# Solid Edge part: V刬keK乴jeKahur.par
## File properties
Author: Egon 815
Template: Normal.par
Last saved by: Egon 815
Revision: 4
Application: Solid Edge
Accuracy: 0,990
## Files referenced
..\Laev.asm
.C:\Kool\3D Modelleerimine\LaevaJoonis\Laev.asm
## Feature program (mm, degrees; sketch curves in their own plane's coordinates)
sketch for "unnamed Protrusion 1" plane through (0, 0, 7184.8312) normal (0, 0, 1) x-axis (1, 0, 0)
  circle centre (11893.7444, -24290.4261) radius 1091.1039
extrude "unnamed Protrusion 1" add to key point along -normal
sketch for "unnamed Cutout 1" plane through (0, -24290.4261, 0) normal (0, -1, 0) x-axis (1, 0, 0)
  line (12191.9132, 6960.694) -> (12191.912, 5564.3945)
  line (12191.912, 5564.3945) -> (11595.5763, 5564.3945)
  line (11595.5763, 5564.3945) -> (11595.5763, 6960.694)
  line (11595.5763, 6960.694) -> (12191.9132, 6960.694)
extrude "unnamed Cutout 1" cut through along +normal
lofted protrusion "unnamed LoftedProtrusion 1"
chamfer "Chamfer_4" setback 150
chamfer "Chamfer_5" setback 50
sketch for "unnamed Cutout 2" plane through (0, -28685.0118, 0) normal (0, -1, 0) x-axis (1, 0, 0)
  circle centre (11893.7444, 6258.1105) radius 125
extrude "unnamed Cutout 2" cut to key point along -normal
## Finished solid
Body 1: solid body, 18 faces, 34 edges, 18 vertices.
  Faces by surface: plane 11, cone 3, cylinder 2, spline 2
  Edges by curve: line 14, circle 11, curve on surface 7, intersection 2
Bounding box of the edges (mm; curved faces can reach further): 2182.208 x 5485.690 x 2152.254, from (10802.6405, -28685.0118, 5032.5774) to (12984.8483, -23199.3222, 7184.8312).
Cylindrical faces by radius (mm): R125 x1, R1091.1039 x1
Conical faces (half-angle, radius in mm at the cone's reference point): 45 deg R1091.1039 x3
Planar faces by outward normal: +x 1, +z 2, -x 1, -y 4, -z 2, oblique 1
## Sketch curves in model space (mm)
line (12191.912, -24290.4261, 5564.3945) -> (11595.5763, -24290.4261, 5564.3945)
line (11595.5763, -24290.4261, 5564.3945) -> (11595.5763, -24290.4261, 6960.694)
line (11595.5763, -24290.4261, 6960.694) -> (12191.9132, -24290.4261, 6960.694)
line (12191.9132, -24290.4261, 6960.694) -> (12191.912, -24290.4261, 5564.3945)
circle centre (11893.7444, -28685.0118, 6258.1105) radius 125
circle centre (11893.7444, -28685.0118, 6258.1105) radius 195.8119
line (11893.7444, -28685.0118, 6062.2986) -> (11893.7444, -28685.0118, 6453.9224)
circle centre (11893.7444, -24290.4261, 6262.5608) radius 298.1681
line (11893.7444, -24290.4261, 6560.7289) -> (11893.7444, -24290.4261, 5964.3926)
line (11893.7444, -28685.0118, 6062.2986) -> (11893.7444, -25409.6126, 5964.3926)
line (11893.7444, -28685.0118, 6062.2986) -> (11893.7444, -28685.0118, 6453.9224)
line (11893.7444, -28685.0118, 6453.9224) -> (11893.7444, -25409.6126, 6560.7289)
line (11893.7444, -25409.6126, 6560.7289) -> (11893.7444, -25409.6126, 5964.3926)
line (11893.7444, -25641.0267, 7085.8609) -> (11893.7444, -23567.2005, 7085.8609)
line (11893.7444, -23567.2005, 7085.8609) -> (11893.7444, -23567.2005, 5032.5774)
line (11893.7444, -23567.2005, 5032.5774) -> (11893.7444, -25641.0267, 5032.5774)
line (11893.7444, -25641.0267, 5032.5774) -> (11893.7444, -25641.0267, 7085.8609)
circle centre (11893.7444, -24290.4261, 7184.8312) radius 1091.1039
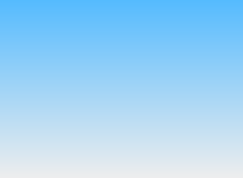
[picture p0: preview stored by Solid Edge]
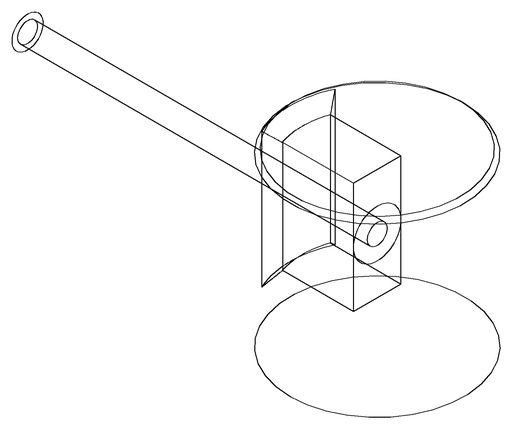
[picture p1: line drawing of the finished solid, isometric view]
